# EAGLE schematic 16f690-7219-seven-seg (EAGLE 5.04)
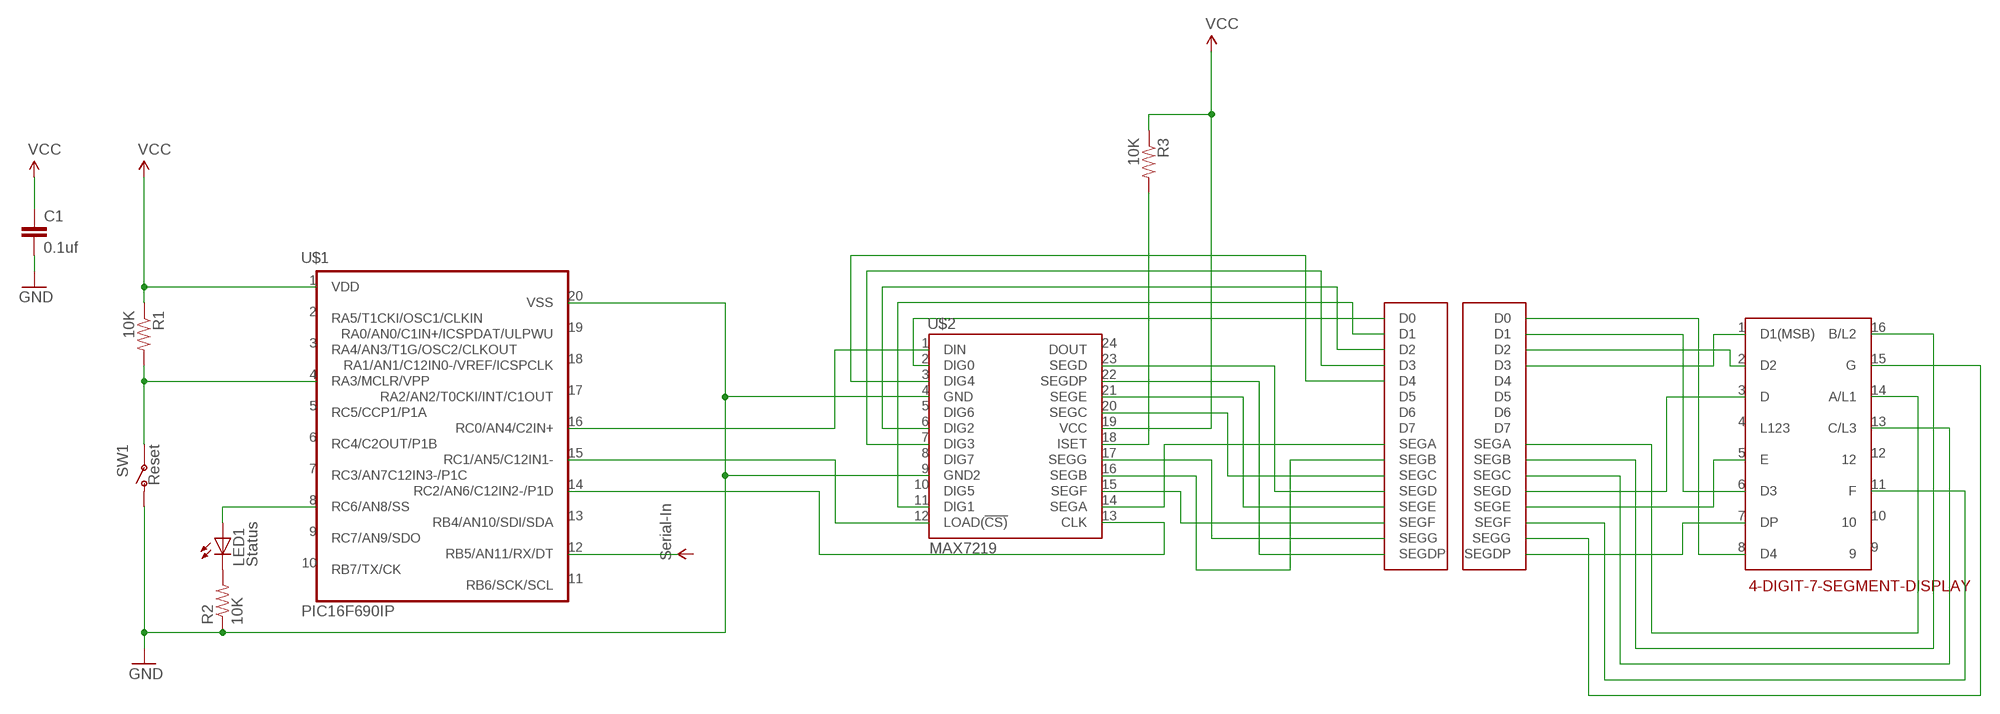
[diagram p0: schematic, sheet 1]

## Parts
4-DIGIT-7-SEGMENT-DISPLAY  SEVEN-SEG-LITEON  [16DIP]
C1  0.1uf  CXXC15B5  [XC15B5]
LED1  Status  LG_T679-E1F1-1  [PLCC2]
R1  10K  RESISTORPTH1  [AXIAL-0.3]
R2  10K  RESISTORPTH1  [AXIAL-0.3]
R3  10K  RESISTORPTH1  [AXIAL-0.3]
SW1  Reset  SWITCH-SPST-2TV  [SWITCH-SPST-VERTICAL]
U$1  PIC16F690IP  [DIL20]
U$2  MAX7219  [DIL24-6]
U$3  SEVEN-SEG-CONN  [16SIL]
U$4  SEVEN-SEG-CONN  [16SIL]

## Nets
GND: C1.2 R2.P$1 SW1.1(O) U$1.20(VSS) U$2.4(GND) U$2.9(GND2)
N$1: U$1.12(RB5/AN11/RX/DT)
N$2: LED1.A U$1.8(RC6/AN8/SS)
N$3: LED1.C R2.P$2
N$4: R1.P$2 SW1.2(P) U$1.4(RA3/MCLR/VPP)
N$5: U$1.16(RC0/AN4/C2IN+) U$2.1(DIN)
N$6: U$2.23(SEGD) U$3.P$12(SEGD)
N$7: U$2.22(SEGDP) U$3.P$13(SEGDP)
N$8: U$2.21(SEGE) U$3.P$14(SEGE)
N$9: U$2.20(SEGC) U$3.P$11(SEGC)
N$10: U$2.17(SEGG) U$3.P$16(SEGG)
N$11: U$2.15(SEGF) U$3.P$15(SEGF)
N$12: U$2.14(SEGA) U$3.P$9(SEGA)
N$13: U$2.16(SEGB) U$3.P$10(SEGB)
N$14: U$2.7(DIG3) U$3.P$4(D3)
N$15: R3.P$2 U$2.18(ISET)
N$16: U$2.3(DIG4) U$3.P$5(D4)
N$17: U$2.2(DIG0) U$3.P$1(D0)
N$18: U$2.11(DIG1) U$3.P$2(D1)
N$19: U$2.6(DIG2) U$3.P$3(D2)
N$20: U$1.15(RC1/AN5/C12IN1-) U$2.12(LOAD(!CS))
N$21: U$1.14(RC2/AN6/C12IN2-/P1D) U$2.13(CLK)
N$22: 4-DIGIT-7-SEGMENT-DISPLAY.8(D4) U$4.P$1(D0)
N$23: 4-DIGIT-7-SEGMENT-DISPLAY.6(D3) U$4.P$2(D1)
N$24: 4-DIGIT-7-SEGMENT-DISPLAY.2(D2) U$4.P$3(D2)
N$25: 4-DIGIT-7-SEGMENT-DISPLAY.1(D1(MSB)) U$4.P$4(D3)
N$26: 4-DIGIT-7-SEGMENT-DISPLAY.14(A/L1) U$4.P$9(SEGA)
N$27: 4-DIGIT-7-SEGMENT-DISPLAY.16(B/L2) U$4.P$10(SEGB)
N$28: 4-DIGIT-7-SEGMENT-DISPLAY.13(C/L3) U$4.P$11(SEGC)
N$29: 4-DIGIT-7-SEGMENT-DISPLAY.3(D) U$4.P$12(SEGD)
N$30: 4-DIGIT-7-SEGMENT-DISPLAY.5(E) U$4.P$14(SEGE)
N$31: 4-DIGIT-7-SEGMENT-DISPLAY.11(F) U$4.P$15(SEGF)
N$32: 4-DIGIT-7-SEGMENT-DISPLAY.15(G) U$4.P$16(SEGG)
N$33: 4-DIGIT-7-SEGMENT-DISPLAY.7(DP) U$4.P$13(SEGDP)
VCC: C1.1 R1.P$1 R3.P$1 U$1.1(VDD) U$2.19(VCC)
Unconnected: 4-DIGIT-7-SEGMENT-DISPLAY.4(L123) 4-DIGIT-7-SEGMENT-DISPLAY.9 4-DIGIT-7-SEGMENT-DISPLAY.10 4-DIGIT-7-SEGMENT-DISPLAY.12 U$1.2(RA5/T1CKI/OSC1/CLKIN) U$1.3(RA4/AN3/T1G/OSC2/CLKOUT) U$1.5(RC5/CCP1/P1A) U$1.6(RC4/C2OUT/P1B) U$1.7(RC3/AN7C12IN3-/P1C) U$1.9(RC7/AN9/SDO) U$1.10(RB7/TX/CK) U$1.11(RB6/SCK/SCL) U$1.13(RB4/AN10/SDI/SDA) U$1.17(RA2/AN2/T0CKI/INT/C1OUT) U$1.18(RA1/AN1/C12IN0-/VREF/ICSPCLK) U$1.19(RA0/AN0/C1IN+/ICSPDAT/ULPWU) U$2.5(DIG6) U$2.8(DIG7) U$2.10(DIG5) U$2.24(DOUT) U$3.P$6(D5) U$3.P$7(D6) U$3.P$8(D7) U$4.P$5(D4) U$4.P$6(D5) U$4.P$7(D6) U$4.P$8(D7)

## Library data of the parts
4-DIGIT-7-SEGMENT-DISPLAY = trl:SEVEN-SEG-LITEON
C1 = rcl:CX: X CAPACITOR
LED1 = led:*_T679-?-1: LC TOPLED® Low Current LED; COLOR: green
R1-R3 = SparkFun:RESISTOR: Resistor
SW1 = SparkFun:SWITCH-SPST-2
U$1 = trl:PIC16F690*: MICROCONTROLLER PIC16F690 18 I/O One 16-bit timer Two 8-bit timer Two comparators Precision internal oscillator-software selectable 8 MHz - 32 KHz SSP w/ I2C Compatible Address mask option EUSART LIN 2.0 Compatible ECCP+ w/ PWM Steering 12 A/D Channels ULPW Enhanced Low Power Timer 1 Timer 1 Gate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
U$2 = trl:MAX7219
U$3 U$4 = trl:SEVEN-SEG-CONN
